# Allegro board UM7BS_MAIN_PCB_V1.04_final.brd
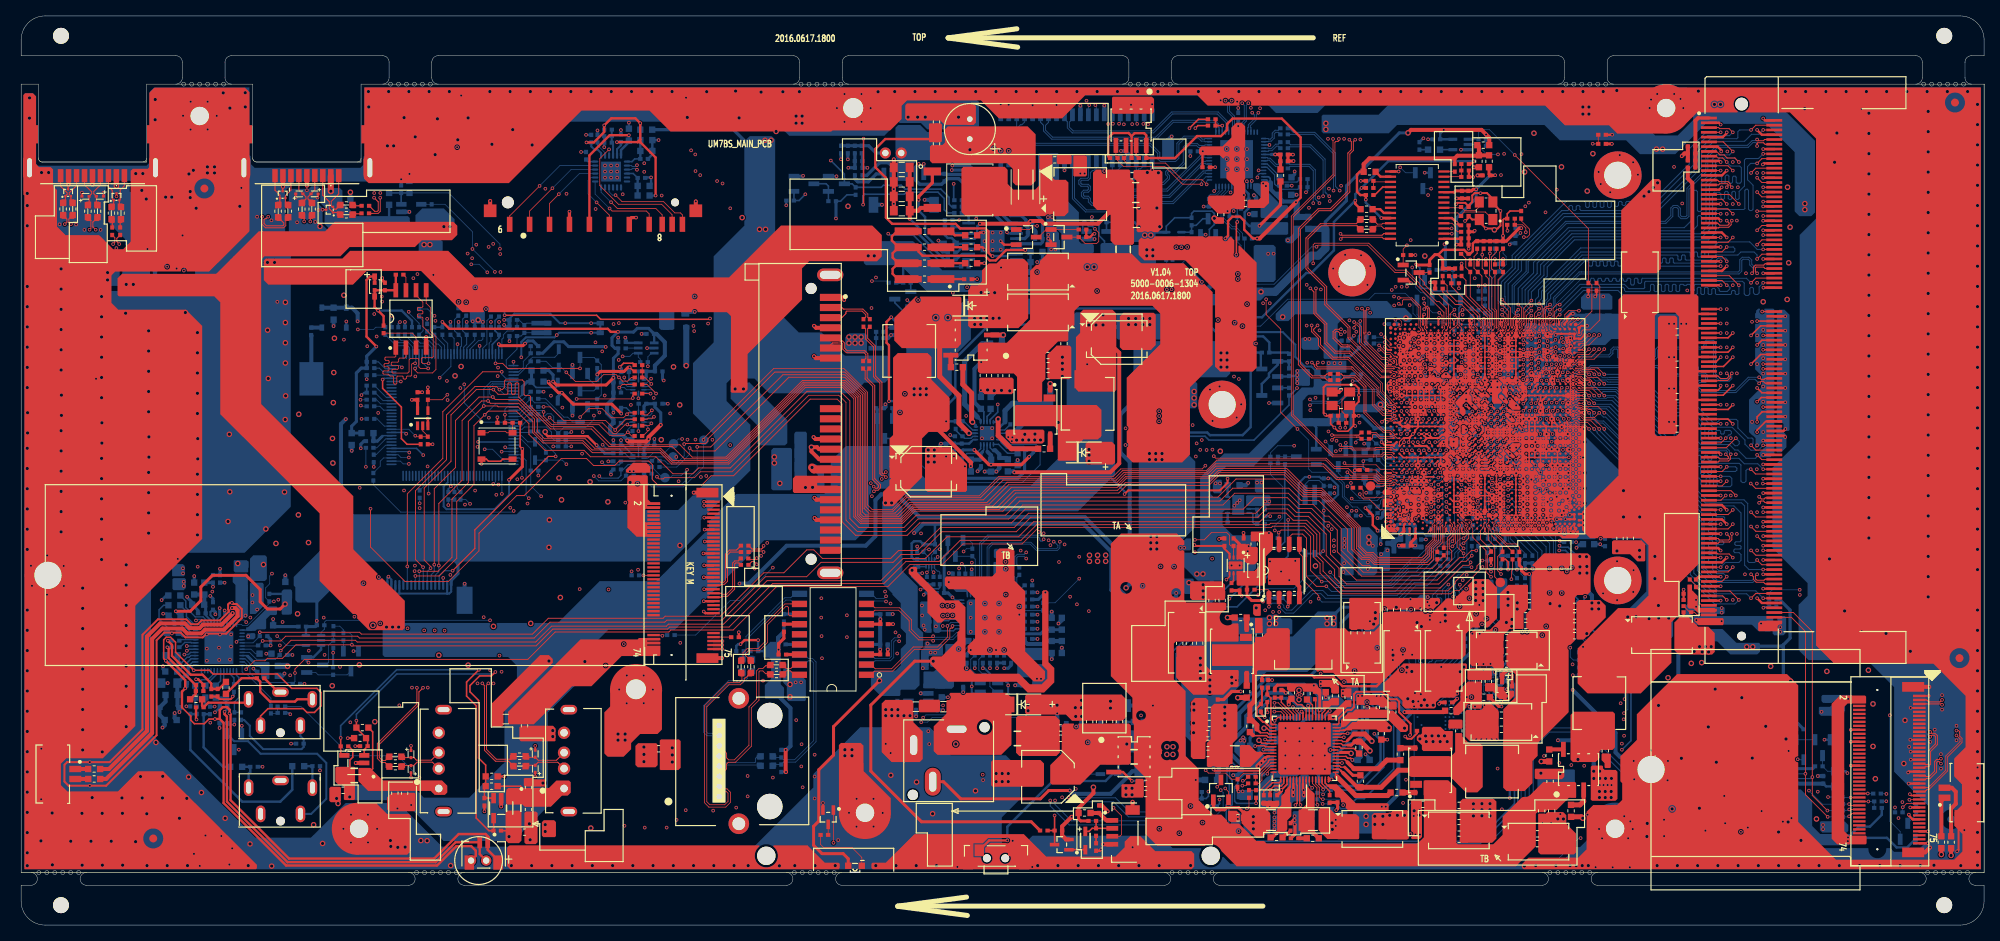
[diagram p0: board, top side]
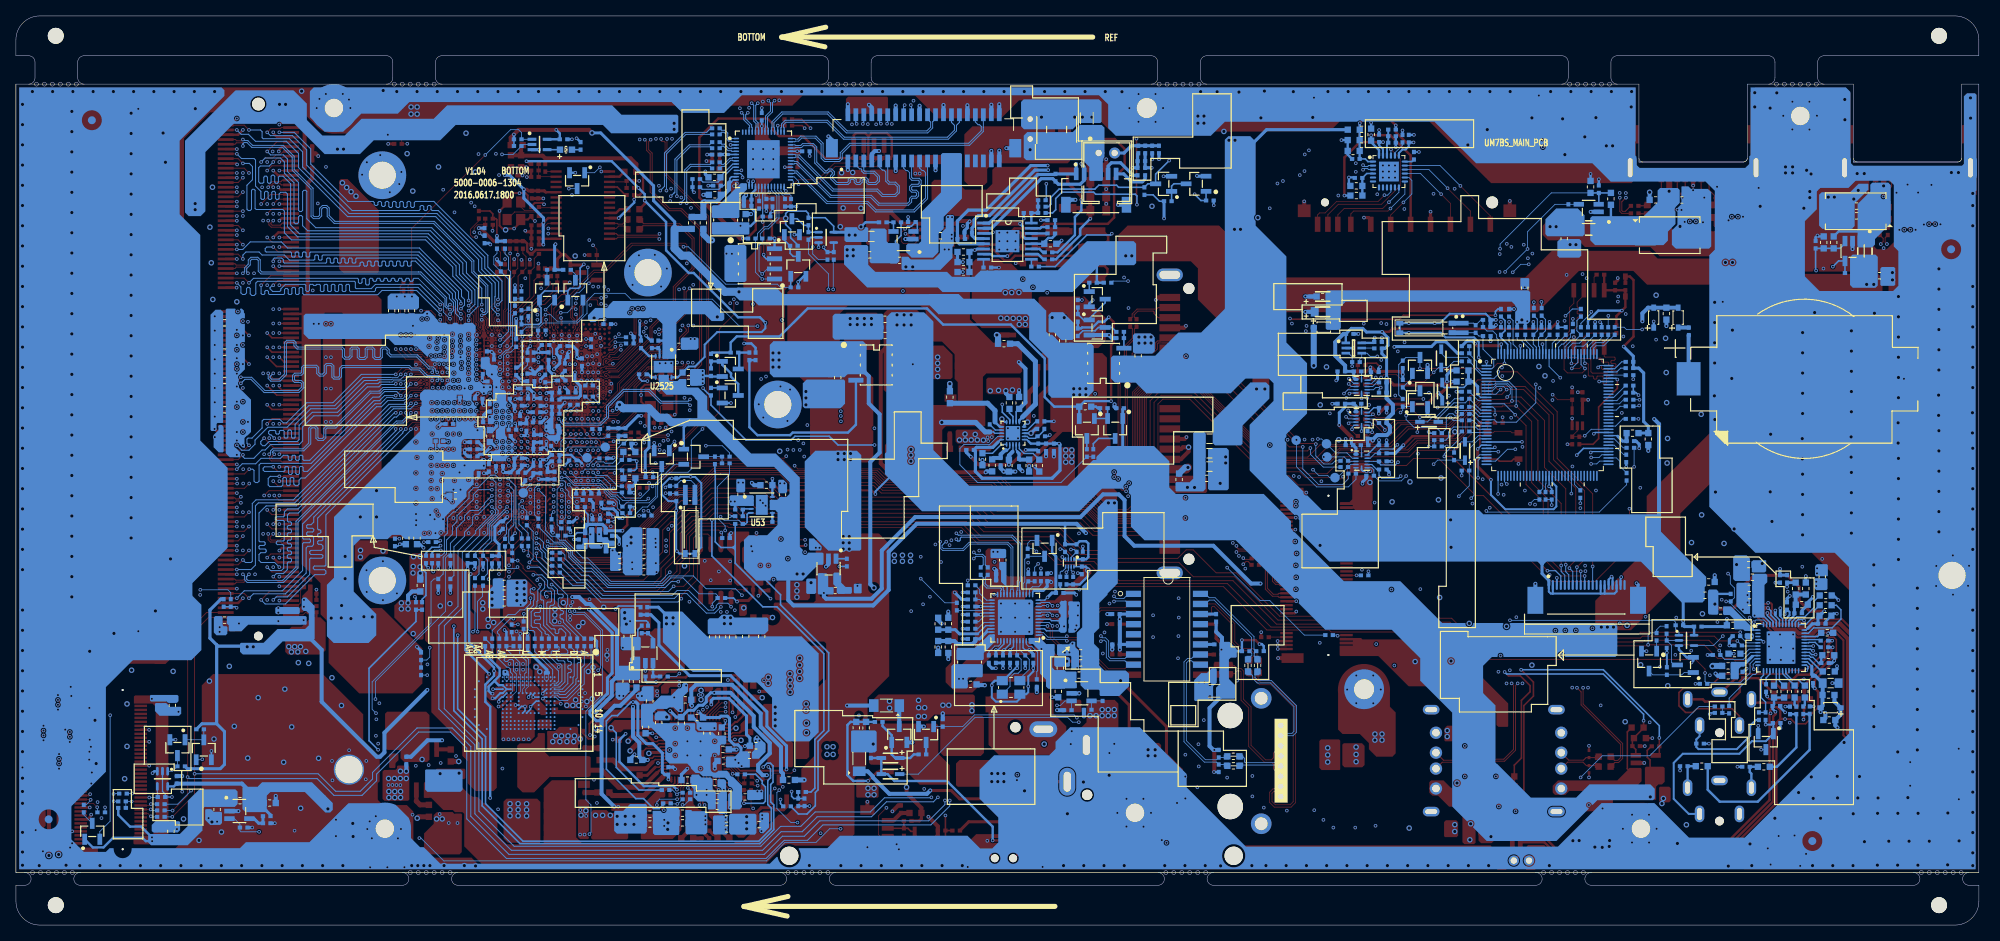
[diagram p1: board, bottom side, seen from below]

Outline 246.3 x 114.17 mm; copper layers: TOP, GND2, LAY3, LAY4, VCC5, BOTTOM. Coordinates in mm from the lower left corner of the outline.

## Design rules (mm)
net group +V3.3A_SW: nets +V3.3A_SW N5599060
net group +V5A_LDO: nets +V5A_LDO N5603445
net group AVDD33_REG: nets AVDD33_REG VDD33
net group DRVH1: nets DRVH1 DRVH1_R
net group DRVH2: nets DRVH2 DRVH2_R
net group DRVL2: nets DRVL2 DRVL2_R
net group EDP_TXN0: nets EDP_TXN0 TXN0_LVDS
net group EDP_TXN1: nets EDP_TXN1 TXN1_LVDS
net group EDP_TXP0: nets EDP_TXP0 TXP0_LVDS
net group EDP_TXP1: nets EDP_TXP1 TXP1_LVDS
net group EMMC_CLK: nets EMMC_CLK N5550076
net group EMMC_CMD: nets EMMC_CMD N5550072
net group EMMC_DATA_0: nets EMMC_DATA_0 N5550120
net group EMMC_DATA_1: nets EMMC_DATA_1 N5550080
net group EMMC_DATA_2: nets EMMC_DATA_2 N5550068
net group EMMC_DATA_3: nets EMMC_DATA_3 N5550084
net group EMMC_DATA_4: nets EMMC_DATA_4 N5550136
net group EMMC_DATA_5: nets EMMC_DATA_5 N5550132
net group EMMC_DATA_6: nets EMMC_DATA_6 N5550116
net group EMMC_DATA_7: nets EMMC_DATA_7 N5550128
net group EMMC_RESET: nets EMMC_RESET N5550124
net group HDA_BITCLK: nets HDA_BITCLK N65040
net group HDA_SDATAIN0: nets HDA_SDATAIN0 N65098
net group HDA_SYNC: nets HDA_SYNC N65002
net group HSON: nets HSON PCIE_RXN0_LAN
net group HSOP: nets HSOP PCIE_RXP0_LAN
net group LAN_TX0N: nets LAN_TX0N N1052644
net group LAN_TX0P: nets LAN_TX0P N1052618
net group LAN_TX1N: nets LAN_TX1N N1052610
net group LAN_TX1P: nets LAN_TX1P N1052708
net group LAN_TX2N: nets LAN_TX2N N1052530
net group LAN_TX2P: nets LAN_TX2P N1052848
net group LAN_TX3N: nets LAN_TX3N N1052868
net group LAN_TX3P: nets LAN_TX3P N1052520
net group LPC_CLK_EC: nets LPC_CLK_EC N83769
net group M_HUB_USB_P1: nets HUB_USB_PN1 HUB_USB_PP1
net group M_LAO1_CLK: nets LAO1_CLKN LAO1_CLKP
net group M_LAO1_DATA0: nets LAO1_DATAN0 LAO1_DATAP0
net group M_LAO1_DATA1: nets LAO1_DATAN1 LAO1_DATAP1
net group M_LAO1_DATA2: nets LAO1_DATAN2 LAO1_DATAP2
net group M_LAO1_DATA3: nets LAO1_DATAN3 LAO1_DATAP3
net group N73565: nets N73565 N73585
net group PCIE_TXN0_LAN: nets N60711 PCIE_TXN0_LAN
net group PCIE_TXN1_WLAN: nets N61460 PCIE_TXN1_WLAN
net group PCIE_TXP0_LAN: nets N60715 PCIE_TXP0_LAN
net group PCIE_TXP1_WLAN: nets N61464 PCIE_TXP1_WLAN
net group PMC_SLP_S0IX: nets N5595026 PMC_SLP_S0IX
net group RSMRST_PWRGD: nets N5599220 RSMRST_PWRGD
net group SATA_RXN0: nets N16952432 SATA_RXN0
net group SATA_RXP0: nets N16952428 SATA_RXP0
net group SPI_CLK: nets N7142816 SPI_CLK
net group SPI_CS0#: nets N7142786 SPI_CS0#
net group SPI_SI: nets N7142806 SPI_SI
net group SPI_SO: nets N7142796 SPI_SO
net group USB3_RX1_N: nets N16888468 USB3_RX1_N
net group USB3_RX1_P: nets N16888504 USB3_RX1_P
net group USB_PN2: nets N17343556 USB_PN2
net group USB_PN3: nets N6564823 USB_PN3
net group USB_PN4: nets N6565949 USB_PN4
net group USB_PP2: nets N17343558 USB_PP2
net group USB_PP3: nets N6564811 USB_PP3
net group USB_PP4: nets N6565995 USB_PP4
net group VCC0_SENSEP_R: nets VCC0_SENSEP_R VCC_SENSEP
net group AUDIO: nets HDA_SDATAOUT
net group CLK: nets CLK_LAN_OE# CLK_WLAN_OE# CLK_WLAN_OE#_MINI DMIC_CLK LPC_CLKRUN# SDMMC1_RCLK SMB_CLK_S2 SMBCLK SOC_SMB_CLK TBCLK
net group COMP&REF: nets AC_VREF MIC1L-VREFO MIC1R-VREFO MIC2-VREFO SODIMM_VREF_CA0 SODIMM_VREF_DQ0
net group DEFAULT: nets 5A_ONOFF +V1.8S A6 A_EARPHONE_SEL AC_PRESENT ADP_IN# BH53 BL_ADJ BT_ON DBG_UART1_RXD DBG_UART1_TXD DDI0_HPD DDI1_HPD DDR3L_EVENT DMIC_DATA DP_HPD EC_MUTE# EDP_BKLCTL EDP_BKLEN EDP_VDDEN EECS EEDI FLASH_TXE FMISO FMOSI FSCE# FSCK GA20_EC GPIO_SUS8 GPIO_SUS9 GPIO_SUS10 GPIO_SUS11 GPO H_PROCHOT# H_RCIN# HD HP_OUT_L HP_OUT_R IRQB ISOLATEB IT8928_VSS KBC_FAN_SPEED LAN_VDDEN_EC LANWAKEB LDO2-CAP LPC_SERIRQ_EC LPCPD# MIC_SEL_SPDIF N46460 N52618 N52622 N53865 N53869 N59327 N59478 N59568 N62557 N62561 N64250 N64254 N64950 N66939 N72611 N72676 N73559 N75766 N77258 N79829 N80354 N81322 N81326 N82446 N82527 N82633 N83371 N83609 N83745 N86700 N86712 N87028 N88403 N89704 N89904 N936455 N964422 N967359 N1003987 N1049332 N1051586 N1061129 N1061133 N1061141 N1062073 N1063057 N1063545 N1064125 N1064657 N1064691 N1064695 N1064865 N1091368 N1121703 N1122397 N1123071 N1123827 N1123831 N1124299 N1124955 N1125039 N1125207 N1125735 N1125963 N1126133 N1126239 N1126307 N1126437 N1126855 N1127021 N1127039 N1127083 N1127147 N1127169 N1127267 N1127313 N1127321 N1127467 N1127901 N1128819 N1129433 N5560544 N5591752 N5599330 N5601032 N5604033 N5614763 N5615595 N5615857 N5617013 N5627138 N5627940 N6729821 N6738242 N6738428 N6738432 N6738496 N6739070 N6739082 N6739106 N16712559 N16714785 PCIE_LAN_WAKE# PCIE_WIFI_WAKE# PD# PM_BATLOW# PM_SLP_S0IX# PM_SLP_S3# PM_SLP_S4# PMC_PLTRST PMC_PWRBTN# PMC_PWRBTN#_EC PMC_SLP_S3 PMC_SLP_S4 PMC_SUS_STAT# PMC_SUSPWRDNACK PMIC_EN POWSW# PROCHOT#_EC PS_LATCH# PWRONLATCHG RSET RUNTIME_SCI#_EC SA0_DIM0 SA1_DIM0 SATA_LED# SECURITY_FLASH SLPS3#_CONTROL SMB_DATA_S2 SMBDATA SMC_ONOFF# SMC_SHUTDOWN# SOC_EXTSMI# SOC_EXTSMI#_EC SOC_FLASHEN SOC_RUNTIME_SCI SOC_SMB_DATA SOC_WAKE_SCI SPKR TBDATA TP_FUSE_LDO TP_FUSE_PWR USB_OC0# USB_OC1# VBAT VFB1 VFB2 VGG_SENSEP VNN_SVID_SENSEP VREG5 WAKE_SCI_EC WIFI_PWRON WIRELESS_ON WP# XTAL1 XTAL2 XTAL25M_OUT
net group DIFFALL: nets L_OUT- M_A_DQS0 M_A_DQS1 M_A_DQS2 M_A_DQS3 M_A_DQS4 M_A_DQS5 M_A_DQS6 M_A_DQS7 M_A_DQS#0 M_A_DQS#1 M_A_DQS#2 M_A_DQS#3 M_A_DQS#4 M_A_DQS#5 M_A_DQS#6 M_A_DQS#7 M_CLK_DDR0 M_CLK_DDR1
net group ISETA: nets ISETA N16970389 N16970394
net group LL1: nets N5614603
net group LPC: nets LPC_SERIRQ
net group M_EDP: nets EDP_AUXN
net group POWER: nets +V1.05A +V1.5S +V1.5S_AUDIO +V1.8A +V1.8A_SPI +V1.8U +V1.15A +V1.15S +V1.24A +V1P8A_EMMC +V2P8A_EMMC +V3.3A +V3.3A_KBC +V3.3A_LDO +V3.3A_PRIME +V3.3A_RTC +V3.3A_WIFI +V3.3AVCC +V3.3S +V3.3S_AUDIO +V5_AVDD +V5_PVDD +V5A +V5S +V15A +V_ADP_IN +V_DC +VCCCFIOAZA +VCCDPYCSIAON_1P24 +VCCPADHSICAON_1P24 +VCCPADSSICAON_1P24 +VCORE +VDDI_EMMC +VEC_LDO +VGG +VNN +VSDIO +VSM +VSM_VTT AC_IN AGND AUDIO_DVDD_IO AVDD2 AXGND DRVH1_R_5614085 DRVH2_5615145 DRVH2_R_5614085 DRVL1 DRVL1_5614359 DRVL1_R DRVL1_R_5614085 DRVL2_5615173 DRVL2_R_5614085 ENSWREG EVDD10 GND GND_EARTH L_OUT+ LAN_CMT LAN_CMT1 LAN_CT LAN_CT1 LAN_N1 LCD_VCC LL1 LL2 LX3 LX4 LX5 N926610 N1061235 N1091486 N1126063 N5595322 N6774197 N6774217 N6835729 N6835771 R_OUT+ R_OUT- REGOUT SPK_L+ SPK_L- SPK_R+ SPK_R- VCC1_USB3.0 VCC_USB2 VDD10 VREG3 VSPI_KBC
net group RST&OK: nets BUF_PLT_RST# CORE_PWROK DDR3_VCCA_PWROK DDR3L_DRAMRST# HDA_RST# PERSTB PMC_RSTBTN RSMRST#_EC WIFI_3P3_RST# WIFI_PERST# WRST#
net group USB3_TX0_N: nets N6563083 N6564657 USB3_TX0_N
net group USB3_TX0_P: nets N6563079 N6564845 USB3_TX0_P
net group USB3_TX1_N: nets N16888488 N16888618 USB3_TX1_N
net group USB3_TX1_P: nets N16888506 N16888527 USB3_TX1_P
net group VCLK: nets N6729809 N6730049 VCLK

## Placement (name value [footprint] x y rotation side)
B1  MIC-2_0  [MIC_FOM6050MP3_190P]  57.4 8.1 180 top
C1  100NF  [CC0402N]  130.15 11.87 180 top
C2  1000pF  [CC0402N]  134.88 9.8 270 top
C3  100NF  [CC0402N]  168.66 61.85 180 top
C4  100NF  [CC0402N]  168.66 61.06 180 top
C5  100NF  [CC0402N]  164.75 68.44 180 top
C6  100NF  [CC0402N]  164.75 69.21 180 top
C7  0.022 nF  [CC0402N]  184.04 48.04 90 bottom
C8  100NF  [CC0402N]  152.89 42.49 90 top
C9  1uF  [CC0402N]  153.4 48.08 270 top
C10  1000pF  [CC0402N]  151.87 42.49 90 top
C11  100NF  [CC0402N]  150.99 48.08 270 top
C12  20PF  [CC0402N]  166.75 63.95 180 top
C13  20PF  [CC0402N]  164.78 63.96 0 top
C14  100NF  [CC0402N]  112.43 46.42 90 bottom
C15  100NF  [CC0402N]  112.56 44.54 270 bottom
C16  12pF  [CC0402N]  163.44 53.71 90 bottom
C17  100NF  [CC0402N]  169.79 55.11 0 bottom
C18  1uF  [CC0603N]  169.32 56.11 180 bottom
C19  1uF  [CC0603N]  169.33 59.42 180 bottom
C20  12pF  [CC0402N]  163.44 55.62 270 bottom
C21  100NF  [CC0402N]  78.98 60.26 0 bottom
C22  100NF  [CC0402N]  74.79 60.26 180 bottom
C23  100NF  [CC0402N]  74.79 58.23 0 bottom
C24  100NF  [CC0402N]  74.79 57.21 0 bottom
C25  1uF  [CC0402N]  183.28 57.72 180 bottom
C26  1uF  [CC0402N]  183.28 58.61 180 bottom
C27  1uF  [CC0402N]  182.25 62.53 270 bottom
C28  1uF  [CC0402N]  183.79 56.83 180 bottom
C29  22uF  [CC0603N]  157.64 36.2 90 bottom
C30  22uF  [CC0603N]  158.89 36.2 90 bottom
C31  22uF  [CC0603N]  156.36 36.17 90 bottom
C32  22uF  [CC0603N]  194.93 36.33 0 top
C33  4.7uF  [CC0603N]  194.93 38.81 0 top
C34  4.7uF  [CC0603N]  186.83 61.41 270 bottom
C35  4.7uF  [CC0603N]  189.25 41.3 180 top
C36  22uF  [CC0603N]  188.79 38.83 180 top
C37  22uF  [CC0603N]  189.26 40.07 180 top
C38  4.7uF  [CC0603N]  194.93 37.56 0 top
C39  4.7uF  [CC0603N]  194.93 40.03 0 top
C40  4.7uF  [CC0603N]  195.57 42.65 270 bottom
C41  22uF  [CC0603N]  188.79 37.62 180 top
C42  1uF  [CC0402N]  188.87 58.87 180 bottom
C43  1uF  [CC0402N]  188.87 59.76 180 bottom
C44  1uF  [CC0402N]  186.85 64.96 90 bottom
C45  1uF  [CC0402N]  175.53 54.17 180 bottom
C46  1uF  [CC0402N]  180.9 59.8 180 bottom
C47  1uF  [CC0402N]  183.28 65.22 180 bottom
C48  1uF  [CC0402N]  188.87 60.64 180 bottom
C49  22uF  [CC0603N]  185.04 42.9 0 bottom
C50  22uF  [CC0603N]  185.04 41.67 0 bottom
C51  22uF  [CC0603N]  185.04 40.45 0 bottom
C52  1uF  [CC0402N]  178.72 62.69 0 bottom
C53  1uF  [CC0402N]  180.48 57.22 90 bottom
C54  22uF  [CC0603N]  170.53 46.41 0 bottom
C55  22uF  [CC0603N]  167.48 49.42 180 bottom
C56  1uF  [CC0402N]  178.58 64.2 0 bottom
C57  1uF  [CC0402N]  182.52 67.38 180 bottom
C58  1uF  [CC0402N]  173.63 54.17 0 bottom
C59  1uF  [CC0402N]  186.66 68.26 180 bottom
C60  1uF  [CC0402N]  184.8 66.11 0 bottom
C61  1uF  [CC0402N]  187.72 69.66 90 bottom
C62  1uF  [CC0402N]  185.18 58.1 90 bottom
C63  1uF  [CC0402N]  187.22 71.57 270 bottom
C64  1uF  [CC0402N]  187.21 63.15 180 bottom
C65  1uF  [CC0402N]  184.69 61.41 0 bottom
C66  1uF  [CC0402N]  186.07 58.1 90 bottom
C67  1uF  [CC0402N]  186.33 70.55 270 bottom
C68  1uF  [CC0402N]  178.58 65.09 0 bottom
C69  1uF  [CC0402N]  178.58 61.91 0 bottom
C70  1uF  [CC0402N]  188.23 66.11 180 bottom
C71  1uF  [CC0402N]  178.58 59.04 0 bottom
C72  1uF  [CC0402N]  176.42 58.36 0 bottom
C73  22uF  [CC0603N]  167.51 44.36 180 bottom
C74  22uF  [CC0603N]  167.51 45.61 180 bottom
C75  22uF  [CC0603N]  170.53 45.02 0 bottom
C76  22uF  [CC0603N]  167.48 48.15 180 bottom
C77  22uF  [CC0603N]  167.48 46.87 180 bottom
C78  1uF  [CC0402N]  180.41 61.09 90 bottom
C79  1uF  [CC0402N]  181.25 68.77 270 bottom
C80  22uF  [CC0603N]  195.98 48.58 270 bottom
C81  1uF  [CC0402N]  179.92 70.03 180 bottom
C82  1uF  [CC0402N]  190.14 66.23 180 bottom
C83  1uF  [CC0402N]  183.53 69.53 270 bottom
C84  1uF  [CC0402N]  181.3 61.09 90 bottom
C85  1uF  [CC0402N]  183.04 63.47 90 bottom
C86  1uF  [CC0402N]  175.28 70.68 90 bottom
C87  22uF  [CC0603N]  196.66 77.17 90 bottom
C88  1uF  [CC0402N]  188.23 57.22 90 bottom
C89  1uF  [CC0402N]  178.58 66.87 0 bottom
C90  1uF  [CC0402N]  179.89 68.63 270 bottom
C91  22uF  [CC0603N]  197.38 48.58 270 bottom
C92  22uF  [CC0603N]  191.15 53.91 0 bottom
C93  22uF  [CC0603N]  197.9 77.15 90 bottom
C94  22uF  [CC0603N]  199.15 77.15 90 bottom
C95  1uF  [CC0402N]  182.14 68.77 270 bottom
C96  1uF  [CC0402N]  180.95 63.13 0 bottom
C97  1uF  [CC0402N]  181.37 57.22 90 bottom
C98  1uF  [CC0402N]  172.36 53.06 0 bottom
C99  1uF  [CC0402N]  173.58 49.68 180 bottom
C100  1uF  [CC0402N]  173.59 48.42 180 bottom
C101  1uF  [CC0402N]  173.48 50.93 0 bottom
C102  1uF  [CC0402N]  170.71 61.91 270 bottom
C103  1uF  [CC0402N]  179.6 56.45 90 bottom
C104  1uF  [CC0402N]  169.82 61.91 270 bottom
C105  1uF  [CC0402N]  173.91 47.66 180 top
C106  1uF  [CC0402N]  180.48 65.67 90 bottom
C107  1uF  [CC0402N]  178.71 56.45 90 bottom
C108  1uF  [CC0402N]  182.39 56.33 90 bottom
C109  1uF  [CC0402N]  178.58 58.23 0 bottom
C110  1uF  [CC0402N]  182.52 66.11 0 bottom
C111  1uF  [CC0402N]  186.96 57.42 90 bottom
C112  1uF  [CC0402N]  185.21 50.23 270 bottom
C113  100NF  [CC0402N]  177.59 98.67 180 bottom
C114  100NF  [CC0402N]  209.07 40.83 0 top
C115  100NF  [CC0402N]  209.07 41.6 0 top
C116  100NF  [CC0402N]  209.6 96.9 0 top
C117  100NF  [CC0402N]  209.6 97.79 0 top
C118  10uF  [CC0603N]  220.11 38.29 0 bottom
C119  100NF  [CC0402N]  220.11 61.41 0 bottom
C120  100NF  [CC0402N]  220.11 60.52 0 bottom
C121  10uF  [CC0603N]  220.11 75.63 0 bottom
C122  10uF  [CC0603N]  220.11 71.95 0 bottom
C123  10uF  [CC0603N]  220.11 68.39 0 bottom
C124  10uF  [CC0603N]  220.11 64.71 0 bottom
C125  10uF  [CC0603N]  207.79 74.49 0 top
C126  10uF  [CC0603N]  207.79 70.42 0 top
C127  10uF  [CC0603N]  207.79 66.36 0 top
C128  10uF  [CC0603N]  207.79 62.3 0 top
C129  1uF  [CC0402N]  219.6 37.15 180 bottom
C130  1uF  [CC0402N]  211.85 38.95 270 bottom
C131  1uF  [CC0402N]  212.74 38.95 270 bottom
C132  1uF  [CC0402N]  210.96 38.95 270 bottom
C133  100NF  [CC0402N]  220.11 76.77 0 bottom
C134  100NF  [CC0402N]  220.11 73.09 0 bottom
C135  100NF  [CC0402N]  220.11 69.53 0 bottom
C136  100NF  [CC0402N]  220.11 65.85 0 bottom
C137  100NF  [CC0402N]  207.92 76.14 0 top
C138  100NF  [CC0402N]  207.92 72.07 0 top
C139  100NF  [CC0402N]  207.92 68.01 0 top
C140  100NF  [CC0402N]  207.92 63.95 0 top
C141  100NF  [CC0402N]  181.85 30.71 90 top
C142  4.7uF  [CC0603N]  182.86 30.58 90 top
C143  100NF  [CC0402N]  182.09 35.49 90 bottom
C144  100NF  [CC0402N]  179.09 27.96 180 top
C145  4.7uF  [CC0603N]  184.09 30.59 90 top
C146  1uF  [CC0402N]  181.15 85.45 180 top
C147  100NF  [CC0402N]  181.15 86.24 180 top
C148  100NF  [CC0402N]  181.58 91.72 90 top
C149  10uF  [CC0603N]  182.92 95.91 90 top
C150  100NF  [CC0402N]  183.85 94.14 0 top
C151  1uF  [CC0402N]  181.15 87.87 180 top
C152  100NF  [CC0402N]  180.78 91.72 90 top
C153  1uF  [CC0402N]  181.19 94.76 180 top
C154  20PF  [CC0402N]  181.15 90.17 180 top
C155  20PF  [CC0402N]  181.15 89.04 180 top
C156  1uF  [CC0603N]  121.71 57.7 270 bottom
C157  10uF  [CC0603N]  128.85 70.25 0 top
C158  10uF  [CC0603N]  128.84 71.52 0 top
C159  10uF  [CC0603N]  130.86 73 270 top
C160  0.1uF  [CC0603N]  128.84 69 180 top
C161  10uF  [CC0603N]  122.17 69 270 top
C163  0.1uF  [CC0603N]  120.73 69.02 90 top
C164  10uF  [CC0603N]  123.58 68.99 270 top
C165  100NF  [CC0402N]  124.12 62.4 270 bottom
C166  100NF  [CC0402N]  118.15 62.78 90 bottom
C167  100NF  [CC0402N]  137.23 75.07 0 bottom
C168  2.2uF  [CC0603N]  137.26 76.07 0 bottom
C171  0.01uF  [CC0402N]  90.79 47.65 0 top
C173  2.2uF  [CC0603N]  114.96 73.37 90 bottom
C174  100NF  [CC0402N]  113.93 73.32 90 bottom
C175  1uF  [CC0603N]  121.64 65.57 270 bottom
C176  0.1uF  [CC0603N]  120.43 65.57 270 bottom
C177  100NF  [CC0402N]  111.12 59.28 90 bottom
C178  100NF  [CC0402N]  111.93 59.28 90 bottom
C179  1uF  [CC0603N]  112.13 65.1 180 bottom
C180  100NF  [CC0402N]  107.76 64.91 0 bottom
C181  100NF  [CC0402N]  109.8 64.92 0 bottom
C182  4.7uF  [CC0603N]  159.39 29.17 270 top
C183  1uF  [CC0603N]  162.31 28.28 180 bottom
C184  4.7uF  [CC0603N]  161.34 29.07 270 top
C185  10uF  [CC0603N]  190.25 10.23 0 top
C186  10uF  [CC0603N]  191.85 18.03 90 top
C187  100NF  [CC0402N]  162.33 28.83 90 top
C188  0.1uF  [CC0603N]  192.05 14.34 270 top
C189  10uF  [CC0603N]  190.25 11.46 0 top
C190  10uF  [CC0603N]  190.8 14.34 270 top
C193  4.7uF  [CC0603N]  163.7 28.5 270 top
C194  4.7uF  [CC0603N]  162.81 25.36 90 bottom
C195  10uF  [CC0603N]  149.43 40.79 90 top
C197  10uF  [CC0603N]  146.6 35.39 270 top
C198  10uF  [CC0603N]  150.69 40.79 90 top
C199  0.1uF  [CC0603N]  147.86 35.4 270 top
C200  10uF  [CC0603N]  145.37 35.38 270 top
C201  4.7uF  [CC0603N]  165.64 25.42 90 bottom
C202  100NF  [CC0402N]  202.94 48.38 270 top
C203  22uF  [CC0603N]  168.9 36.7 90 top
C204  22uF  [CC0603N]  201.92 48.57 270 top
C205  22uF  [CC0603N]  200.62 48.57 270 top
C206  22uF  [CC0603N]  173.48 39.6 90 top
C207  22uF  [CC0603N]  171.8 39.58 90 top
C208  22uF  [CC0603N]  175.26 39.6 90 top
C209  22uF  [CC0603N]  167.25 36.7 90 top
C210  10uF  [CC0603N]  170.67 24.04 270 top
C211  0.1u  [CC0603N]  154.18 24.98 90 top
C212  2.2uF  [CC0603N]  153.45 22.52 0 bottom
C213  0.1u  [CC0603N]  167.87 22.29 270 top
C214  10uF  [CC0603N]  157.53 20.61 0 bottom
C215  2.2uF  [CC0603N]  168.46 20.74 0 bottom
C216  10uF  [CC0603N]  180.42 15.03 0 top
C217  0.1uF  [CC0603N]  175.9 15.17 180 top
C218  2.2uF  [CC0603N]  160.83 26.06 0 bottom
C219  10uF  [CC0603N]  180.42 10.75 0 top
C220  10uF  [CC0603N]  180.42 12.22 0 top
C221  4.7uF  [CC0603N]  157.61 22.06 180 bottom
C222  10uF  [CC0603N]  180.42 13.66 0 top
C223  0.1u  [CC0603N]  168.05 18.05 90 top
C224  22uF  [CC0603N]  185.73 26.36 180 top
C225  22uF  [CC0603N]  185.73 24.58 180 top
C226  22uF  [CC0603N]  186.39 34.44 180 top
C227  22uF  [CC0603N]  186.4 32.77 180 top
C228  22uF  [CC0603N]  186.39 36.11 180 top
C229  22uF  [CC0603N]  149.08 25.32 180 top
C230  22uF  [CC0603N]  149.1 26.96 180 top
C231  22uF  [CC0603N]  152.72 36.23 90 bottom
C232  22uF  [CC0603N]  154.74 36.23 90 bottom
C233  100NF  [CC0402N]  155.92 15.83 90 top
C234  100NF  [CC0402N]  156.72 15.84 90 top
C235  100NF  [CC0402N]  157.61 15.84 90 top
C236  10uF  [CC0603N]  158.59 17.9 180 bottom
C237  10uF  [CC0603N]  162.04 18.21 0 bottom
C238  1uF  [CC0402N]  164.44 19.36 90 bottom
C239  22uF  [CC0603N]  166.76 13.93 0 bottom
C240  22uF  [CC0603N]  166.75 12.69 0 bottom
C241  22uF  [CC0603N]  162.67 14.05 180 bottom
C242  22uF  [CC0603N]  162.67 12.83 180 bottom
C243  100NF  [CC0402N]  165.19 15.88 90 top
C244  10uF  [CC0603N]  172.11 26.75 270 top
C245  10uF  [CC0603N]  169.62 27.31 270 top
C246  10uF  [CC0603N]  170.85 27.31 270 top
C247  10uF  [CC0603N]  168.1 27.37 270 top
C249  22uF  [CC0603N]  157.13 12.08 0 bottom
C250  22uF  [CC0603N]  153.06 12.62 180 bottom
C251  22uF  [CC0603N]  152.68 13.46 180 top
C252  22uF  [CC0603N]  157.13 13.33 0 bottom
C253  10uF  [CC0603N]  137.25 74.03 0 bottom
C254  0.01uF  [CC0402N]  144.2 68.6 90 bottom
C255  10uF  [CC0603N]  143.19 68.74 270 bottom
C256  0.01uF  [CC0402N]  153.49 71.42 270 bottom
C257  10uF  [CC0603N]  116.26 74.11 90 bottom
C258  0.01uF  [CC0402N]  104.43 71.62 270 bottom
C259  10uF  [CC0603N]  105.49 71.48 90 bottom
C260  0.01uF  [CC0402N]  107.75 73.71 180 bottom
C261  10uF  [CC0805N]  96.53 59.24 180 bottom
C263  0.01uF  [CC0402N]  90.81 46.85 0 top
C264  1uF  [CC0603N]  96.89 56.1 180 bottom
C265  1uF  [CC0603N]  169.61 36.27 90 bottom
C266  100NF  [CC0402N]  170.75 30.57 90 bottom
C267  1uF  [CC0603N]  169.73 30.64 270 bottom
C268  0.01uF  [CC0402N]  166.99 37.13 270 bottom
C281  100NF  [CC0402N]  158.47 97.55 180 bottom
C283  100NF  [CC0402N]  129.8 87.6 0 bottom
C284  10uF  [CC0603N]  130.29 86.56 180 bottom
C286  0.01uF  [CC0402N]  137.53 88.25 180 bottom
C287  100NF  [CC0402N]  158.47 98.32 180 bottom
C288  10uF  [CC0603N]  135.43 83.47 180 bottom
C290  100NF  [CC0402N]  158.47 95.02 180 bottom
C292  100NF  [CC0402N]  158.47 95.78 0 bottom
C295  100NF  [CC0402N]  152.72 101.52 270 bottom
C296  0.01uF  [CC0402N]  90.77 46.04 0 top
C297  4.7uF  [CC1206N]  111.94 101.31 90 bottom
C298  10uF  [CC1210N]  115.67 99.9 90 bottom
C299  100NF  [CC0402N]  158.47 100.06 0 bottom
C300  2.2uF  [CC0603N]  158.65 93.9 180 bottom
C301  1uF  [CC0402N]  158.34 92.85 180 bottom
C302  10uF  [CC1210N]  139.85 91.93 0 top
C303  100NF  [CC0402N]  158.47 99.29 0 bottom
C304  100NF  [CC0402N]  147.18 97.17 0 bottom
C305  1uF  [CC0402N]  158.48 95.94 180 top
C306  100NF  [CC0402N]  158.48 96.76 180 top
C307  0.01uF  [CC0402N]  158.47 96.75 180 bottom
C308  10uF  [CC0603N]  158.61 91.71 0 bottom
C309  10uF  [CC0603N]  154.75 88.53 90 bottom
C310  100NF  [CC0402N]  154.49 91.1 180 bottom
C311  0.01uF  [CC0402N]  154.49 90.32 180 bottom
C312  0.01uF  [CC0402N]  90.79 45.23 0 top
C313  100NF  [CC0402N]  77.36 56.65 270 top
C314  100NF  [CC0402N]  78.2 56.65 270 top
C315  10uF  [CC0603N]  63.16 25.03 90 top
C316  100NF  [CC0402N]  64.23 25.21 90 top
C319  10uF  [CC0805N]  96.53 57.57 0 bottom
C320  0.1u  [CC0402N]  96.89 55.07 0 bottom
C323  20PF  [CC0402N]  119.66 33.4 270 bottom
C324  20PF  [CC0402N]  120.68 33.4 270 bottom
C325  10uF  [CC0603N]  115.51 29.35 270 bottom
C326  100NF  [CC0402N]  115.79 34.19 180 bottom
C327  100NF  [CC0402N]  126.39 40 0 bottom
C328  100NF  [CC0402N]  115.34 41.7 180 bottom
C329  100NF  [CC0402N]  123.34 33.4 270 bottom
C330  100NF  [CC0402N]  115.79 34.98 180 bottom
C331  100NF  [CC0402N]  121.56 33.4 270 bottom
C332  10uF  [CC0603N]  112.7 34.17 0 bottom
C333  1uF  [CC0603N]  112.7 32.92 0 bottom
C334  100NF  [CC0402N]  111.82 27.03 180 bottom
C335  4.7uF  [CC0603N]  129.31 34.92 90 bottom
C336  100NF  [CC0402N]  126.39 35.94 0 bottom
C337  4.7uF  [CC0603N]  126.52 30.22 0 bottom
C338  100NF  [CC0402N]  114.45 40.38 180 bottom
C339  100NF  [CC0402N]  114.45 39.24 180 bottom
C340  100NF  [CC0402N]  114.45 36.99 180 bottom
C341  100NF  [CC0402N]  118.64 33.4 270 bottom
C342  100NF  [CC0402N]  116.9 43.65 90 bottom
C343  100NF  [CC0402N]  126.39 38.98 0 bottom
C344  100NF  [CC0402N]  114.45 38.09 180 bottom
C345  100NF  [CC0402N]  122.45 33.4 270 bottom
C346  100NF  [CC0402N]  125.25 44.44 270 bottom
C347  100NF  [CC0402N]  124.36 44.44 270 bottom
C348  1uF  [CC0402N]  122.84 44.08 180 bottom
C349  100NF  [CC0402N]  122.84 43.28 0 bottom
C350  100NF  [CC0402N]  108.26 33.98 180 top
C351  100NF  [CC0402N]  108.26 35.24 180 bottom
C352  100NF  [CC0402N]  95.49 30.89 0 bottom
C353  0.01uF  [CC0402N]  95.49 31.78 180 bottom
C354  1000pF  [CC1206N]  95.93 29.42 180 bottom
C355  1000pF  [CC0402N]  95.93 29.42 0 bottom
C356  0.01uF  [CC0402N]  80 21.13 180 top
C357  1000pF  [CC0402N]  80 20.33 180 top
C358  100NF  [CC0402N]  108.29 37.79 180 top
C359  100NF  [CC0402N]  108.28 39.05 180 bottom
C360  1uF  [CC0603N]  18.76 25.75 0 bottom
C361  1uF  [CC0603N]  28.9 45.27 180 bottom
C362  100NF  [CC0402N]  24.95 43.48 90 bottom
C363  4.7uF  [CC0603N]  18.89 33.88 180 bottom
C364  2.2uF  [CC0603N]  19.03 36.7 180 bottom
C365  100NF  [CC0402N]  19.3 32.9 0 bottom
C366  10uF  [CC0603N]  18.84 31.84 180 bottom
C367  10uF  [CC0603N]  19.25 38.85 0 bottom
C368  100NF  [CC0402N]  19.71 37.83 0 bottom
C369  100NF  [CC0402N]  20.82 30.85 90 bottom
C370  10uF  [CC0805N]  18.6 30.39 180 bottom
C371  100NF  [CC0402N]  22.68 39.16 0 bottom
C372  10uF  [CC0603N]  22.22 40.23 180 bottom
C373  2.2uF  [CC0603N]  24.43 29.32 90 bottom
C374  1uF  [CC0603N]  33.9 43.09 180 bottom
C375  2.2uF  [CC0603N]  19.23 40.16 180 bottom
C376  10uF  [CC0603N]  19.22 41.39 0 bottom
C377  2.2uF  [CC0603N]  25.7 29.32 90 bottom
C378  4.7uF  [CC0603N]  21.84 29.33 90 bottom
C379  4.7uF  [CC0603N]  23.12 29.33 90 bottom
C380  100NF  [CC0402N]  28.54 39.37 180 bottom
C381  10uF  [CC0603N]  28.8 42.28 0 bottom
C382  100NF  [CC0402N]  24.07 40.07 270 bottom
C383  10uF  [CC0603N]  28.78 40.57 0 bottom
C384  100NF  [CC0402N]  31.34 27.05 90 bottom
C385  10uF  [CC0603N]  30.67 34.08 180 bottom
C386  10uF  [CC0603N]  30.87 37.64 0 bottom
C387  100NF  [CC0402N]  29.1 36.8 90 bottom
C388  100NF  [CC0402N]  29.67 32.27 90 bottom
C389  22pF  [CC0402N]  30.21 35.11 180 bottom
C390  22pF  [CC0402N]  34.54 30.29 180 bottom
C391  22pF  [CC0402N]  32.91 33.92 180 bottom
C392  22pF  [CC0402N]  30.42 36.28 180 bottom
C393  100pF  [CC0402N]  29.23 19.88 0 bottom
C394  100pF  [CC0402N]  37.02 19.95 0 bottom
C395  100NF  [CC0402N]  35.27 37.48 0 bottom
C396  100pF  [CC0402N]  22.4 30.15 0 top
C397  100pF  [CC0402N]  24.66 29.18 270 top
C398  100pF  [CC0402N]  30.04 31 0 top
C399  100pF  [CC0402N]  22.42 27.34 180 top
C400  10uF  [CC0603N]  226.85 11.77 90 bottom
C401  100NF  [CC0402N]  228.74 11.45 270 bottom
C402  100NF  [CC0402N]  227.92 11.46 270 bottom
C405  100NF  [CC0402N]  226.13 18.24 90 bottom
C409  100NF  [CC0402N]  222.13 14.7 90 bottom
C410  1uF  [CC0603N]  221.06 14.51 270 bottom
C411  1uF  [CC0603N]  214.45 15.33 180 bottom
C412  100NF  [CC0402N]  214.83 12.79 0 bottom
C413  100NF  [CC0402N]  78.95 74.24 180 bottom
C414  100NF  [CC0402N]  75.39 73.22 180 bottom
C415  10uF  [CC0603N]  56.98 79.98 270 bottom
C416  10uF  [CC0603N]  41.48 61.03 90 bottom
C417  100NF  [CC0402N]  43.73 60.77 180 bottom
C418  100NF  [CC0402N]  80 69.53 0 bottom
C419  100NF  [CC0402N]  75.79 69.43 180 bottom
C420  100NF  [CC0402N]  80 65.47 0 bottom
C421  100NF  [CC0402N]  74.79 64.96 180 bottom
C422  1uF  [CC0402N]  60.24 63.07 0 top
C423  10pF  [CC0402N]  61.75 75.11 180 bottom
C424  100NF  [CC0402N]  64.41 66.98 0 bottom
C425  10pF  [CC0402N]  61.75 73.97 180 bottom
C426  100NF  [CC0402N]  49.73 66.43 270 top
C427  100NF  [CC0402N]  45.64 80.19 90 top
C428  47pF  [CC0402N]  51.04 66.44 90 top
C429  0.01uF  [CC0402N]  106.49 75.61 90 top
C432  0.01uF  [CC0402N]  105.69 75.61 90 top
C433  0.01uF  [CC0402N]  106.42 70.36 90 top
C434  0.01uF  [CC0402N]  105.65 70.36 90 top
C435  10uF  [CC0603N]  150.11 54.04 90 bottom
C436  1uF  [CC0603N]  152.13 55.24 0 bottom
C437  10uF  [CC0603N]  12.47 81.54 180 bottom
C438  10uF  [CC0603N]  15.34 89.06 0 bottom
C439  10uF  [CC0603N]  15.34 90.29 0 bottom
C440  1000pF  [CC0402N]  13.76 92.67 0 bottom
C441  100NF  [CC0402N]  20.49 85.45 90 bottom
C442  100NF  [CC0402N]  11.43 87.13 270 top
C443  100NF  [CC0402N]  12.43 87.13 270 top
C444  10uF  [CC0603N]  52.04 86.19 270 bottom
C445  10uF  [CC0603N]  37.27 91.05 180 bottom
C446  10uF  [CC0603N]  40.56 91.06 0 bottom
C447  1000pF  [CC0402N]  37.42 92.08 180 bottom
C448  100NF  [CC0402N]  47.69 92.41 90 bottom
C449  10uF  [CC0603N]  40.4 16.93 180 top
C450  10uF  [CC0603N]  46.9 16.57 270 top
C451  10uF  [CC0603N]  48.12 16.55 270 top
C452  1000pF  [CC0402N]  49.11 16.74 270 top
C453  100NF  [CC0402N]  43 22.47 180 top
C454  10uF  [CC0603N]  63.16 11.67 0 top
C455  10uF  [CC0603N]  63.66 17.27 90 top
C456  10uF  [CC0603N]  63.66 14.52 270 top
C457  1000pF  [CC0402N]  64.74 17.41 90 top
C458  100NF  [CC0402N]  58.13 15.47 270 top
C459  0.1uF  [CC0603N]  136.57 25.55 270 top
C460  0.1uF  [CC0603N]  137.82 25.55 270 top
C461  2.2uF  [CC0805N]  112.27 27.42 0 top
C462  10uF  [CC0603N]  134.07 25.54 90 top
C464  0.1uF  [CC0603N]  135.32 25.53 270 top
C465  0.1uF  [CC0603N]  139.63 24.77 270 bottom
C466  10uF  [CC0603N]  141.1 16.52 180 top
C468  0.1uF  [CC0603N]  141.1 17.79 0 top
C488  1uF  [CC0603N]  39.21 76.78 90 bottom
C527  1uF  [CC0402N]  146.43 46.93 90 bottom
C557  1uF  [CC0402N]  145.77 42.23 0 bottom
C560  1000pF  [CC0402N]  179.36 24.52 90 top
C561  1000pF  [CC0402N]  155.13 38.68 270 top
C562  1000pF  [CC0402N]  198.99 19.6 90 top
C565  100NF  [CC0402N]  135.25 14.55 270 top
C566  100NF  [CC0402N]  76.38 56.42 180 bottom
C603  10uF  [CC1210N]  139.93 88.8 0 top
C607  0.1uF  [CC0603N]  139.38 94.1 180 top
C691  4700pF  [CC0402N]  159.79 10.9 180 top
C700  4.7uF  [CC0603N]  78.45 98.57 0 bottom
C701  0.1u  [CC0402N]  78.18 96.21 0 bottom
C702  0.1u  [CC0402N]  77.84 93.82 180 bottom
C703  2.2uF  [CC0603N]  78.11 92.82 0 bottom
C704  4.7uF  [CC0603N]  76.26 99.26 90 bottom
C705  0.1u  [CC0402N]  71.54 98.76 90 bottom
C706  1uF  [CC0402N]  70.89 96.61 270 bottom
C707  0.1u  [CC0402N]  73.64 98.25 180 bottom
C708  4.7uF  [CC0603N]  78.45 97.21 0 bottom
C710  0.1u  [CC0402N]  75.26 98.79 270 bottom
C727  470nF  [CC0402N]  116.39 88.52 180 bottom
C799  0.01uF  [CC0402N]  228.47 28.01 90 bottom
C800  10uF  [CC0603N]  226.68 27.59 90 bottom
C801  100NF  [CC0402N]  227.69 28.01 90 bottom
C822  4700pF  [CC0402N]  159.28 12.33 90 top
C823  100NF  [CC0402N]  148.14 15.42 90 bottom
C826  22uF  [CC0603N]  148.91 21.56 180 top
C827  22uF  [CC0603N]  148.91 22.81 180 top
C828  22uF  [CC0603N]  148.91 24.04 180 top
C829  10uF  [CC0603N]  158.3 16.15 180 bottom
C830  10uF  [CC0603N]  158.32 14.92 180 bottom
C831  10uF  [CC0603N]  154.25 21.32 180 bottom
C942  0.1u  [CC0402N]  129.8 88.4 0 bottom
C992  2.2uF  [CC0603N]  116.51 85.55 180 bottom
C2762  100NF  [CC0402N]  43.19 89.37 0 top
C2763  100NF  [CC0402N]  43.19 90.32 0 top
C2833  10uF  [CC5750N]  115.71 99.91 90 bottom
C2834  10uF  [CC0603N]  155.33 54.08 90 bottom
C2835  10uF  [CC0603N]  163.11 72.67 180 bottom
C2836  1uF  [CC0603N]  161.9 69.39 180 bottom
C2837  10uF  [CC0603N]  161.91 68.15 180 bottom
C2838  1000pF  [CC0402N]  131.94 96.09 0 top
CN1  0705A1BA52E/0705A1BE52E  [SMD-DDR-60X1020P-204N-R]  215.88 69.7 90 top
CN3  SAF-0001BX-41-5N-0XX  [SMD-SATA-127P-22AN-L-KX]  100.47 62.94 270 top
CN6  RJB-2X08X-XX-XX-XXX  [TH-RJ45-127P-8N]  95.04 20.6 90 top
CN7  WB1012US-02T5  [SMD-CN-100P-2N-V-CB]  58.04 7.85 0 top
CN9  213MAAA32  [SMD-M2PCIE-50X750P-75BN]  83.11 43.92 270 top
CN10  1.25T-2-2PWB-T  [SMD-CN-125P-2WBN]  243.82 16.61 90 top
CN11  F2T20U-XXT3-E  [SMD-CN-50P-20N-H]  49.21 40.38 180 bottom
CN12  1.25T-2-2PWB-T  [SMD-CN-125P-2WBN]  4.3 18.97 270 top
CN18  CN-USB-9+4  [SMD-USB-100P-9AN]  35.85 95.1 180 top
CN19  SHNG04X-XX-XX-XXX  [TH-USB-250PX200P-4BN]  53.21 20.65 90 top
CN20  SHNG04X-XX-XX-XXX  [TH-USB-250PX200P-4BN]  68.93 20.65 90 top
CN21  CDZ-1.7-V10-2010  [TH-DCIN-540P-3N]  116.39 20.6 270 top
CN22  WB2012DR-02T2  [TH-CN-200P-2N-H]  109.44 96.95 180 bottom
CN23  MC38-1200X-XXD  [SMD-SD-250P-9N]  70.6 97.25 180 top
CN24  BS-06-A3A0J001  [SMD-BATTERY-2900P-2N]  21.92 68.6 0 bottom
CN25  WB1012US-04T5  [SMD-CN-100P-4N-V-CB]  139.46 11.65 90 top
CN26  M.2 SOCKET-1 SD/DP KEY E  [SMD-M2PCIE-50X750P-75AN]  234.41 19.52 270 top
CN35  WB1003UR-40XXB  [SMD-CN-100P-40AN-H]  132.41 98.85 180 bottom
CN40  P5C08F-401665-XX  [SMD-CN-200P-8N]  113.35 84.12 90 top
CP1  330uF  [CCP7343N]  173.3 33.16 270 top
CP3  330uF  [CCP7343N]  169.55 12.07 0 top
CP4  330uF  [CCP7343N]  203.11 80.72 90 top
CP5  150uF  [CCP7343N]  137.47 73.58 0 top
CP6  220UF  [CAE630W570HN]  137.47 73.58 0 top
CP7  220UF  [CAE630W570HN]  113.57 56.93 0 top
CP8  150uF  [CCP7343N]  113.57 56.93 0 top
CP9  330uF  [CCP7343N]  205.89 36.42 0 top
CP10  330uF  [CCP7343N]  178.48 33.17 270 top
CP11  330uF  [CCP7343N]  168.25 36.7 90 top
CP12  330uF  [CCP7343N]  186.4 34.47 180 top
CP13  330uF  [CCP7343N]  185.73 25.5 180 top
CP14  100uF  [CAE660W800HN]  128.84 18.62 180 top
CP15  330uF  [CCP7343N]  127.59 82.06 180 top
CP16  330uF  [CCP7343N]  127.59 76.94 180 top
CP17  330uF  [CCP7343N]  146.26 35.45 270 top
CP18  330uF  [CCP7343N]  190.39 10.48 0 top
CP19  330uF  [CCP7343N]  180.4 11.88 0 top
CP20  330uF  [CCP7343N]  38.79 86.64 180 bottom
CP21  330uF  [CCP7343N]  15.46 89.64 0 bottom
CP50  10UF  [THR-CPR50-630X1100N]  119.04 99.96 90 top
D1  BAT54WS-7-F  [SOD1713N]  154.54 44.53 270 top
D2  SK34L  [SOD5225N]  133.33 59.35 0 top
D3  SK34L  [SOD5225N]  119.08 77.78 0 top
D4  D_2PN  [SOT95P280-3N]  108.38 62.36 270 bottom
D5  D_2PN  [SOT95P280-3N]  111.93 62.36 270 bottom
D8  1SS355TE17  [SOD2514N]  67.33 66.98 270 bottom
D9  1SS355TE17  [SOD2514N]  68.98 63.19 0 bottom
D10  1SS355TE17  [SOD2514N]  64.49 59.53 270 bottom
D11  1SS355TE17  [SOD2514N]  67.46 71.17 270 bottom
D12  BAT54WS-7-F  [SOD1713N]  44.36 80.19 270 top
D13  AOZ8231  [SOD0806N]  9.89 91.52 0 top
D14  AOZ8231  [SOD0806N]  8.08 91.52 180 top
D17  AOZ8231  [SOD0806N]  48.92 19.58 270 top
D18  AOZ8231  [SOD0806N]  48.92 21.48 90 top
D19  AOZ8231  [SOD0806N]  64.51 19.62 270 top
D20  AOZ8231  [SOD0806N]  64.51 21.52 90 top
D21  SK34L  [SOD5225N]  125.74 27.71 0 top
D22  1SS355TE17  [SOD2514N]  136.57 20.98 180 bottom
D23  1SS355TE17  [SOD2514N]  136.57 18.96 180 bottom
D26  BAT54WS-7-F  [SOD1713N]  37.73 76.28 90 bottom
D27  BAT54WS-7-F  [SOD1713N]  40.8 76.28 90 bottom
D28  1SS355TE17  [SOD2514N]  133.53 10.62 90 top
D29  1SS355TE17  [SOD2514N]  82.34 78.94 0 bottom
D30  BAT54WS-7-F  [SOD1713N]  82.2 75.07 180 bottom
D31  1SS355TE17  [SOD2514N]  82.34 77 0 bottom
D38  B2100  [SOD5336N]  126.03 92.72 90 top
D42  DFLS1100-7  [SOD2818N]  126.06 93 90 top
D43  BAT54WS-7-F  [SOD1713N]  18.61 27.3 0 bottom
D44  BAT54WS-7-F  [SOD1713N]  185.82 30.05 270 top
D2512  AOZ8231  [SOD0806N]  34.91 91.82 180 top
D2513  AOZ8231  [SOD0806N]  36.81 91.81 0 top
F2  1206L110//NANOSMDC110F  [F1206N]  14.3 84.63 90 bottom
F3  1206L110//NANOSMDC110F  [F1206N]  48.96 87.54 180 bottom
F4  1206L110//NANOSMDC110F  [F1206N]  41.8 18.78 0 top
F5  1206L110//NANOSMDC110F  [F1206N]  61.81 14.68 90 top
F6  3216FF-5A  [F1206N]  139.65 21.12 180 top
F8  3216FF-5A  [F1206N]  125.01 23.43 180 top
F9  0.5A  [F1206N]  138.29 84.86 270 top
FB1  220  [FB0603N]  184.19 95.91 90 top
FB2  220  [FB0603N]  169.2 94.59 0 top
FB4  180  [FB0603N]  150.53 89.22 90 top
FB5  180  [FB0603N]  158.02 94.13 270 top
FB6  180  [FB0603N]  160.05 88.17 270 bottom
FB7  47  [FB0603N]  79.99 22.14 0 top
FB8  180ohm  [FB0603N]  18.87 28.9 180 bottom
FB9  180ohm  [FB0603N]  28.43 43.69 0 bottom
FB10  180ohm  [FB0603N]  21.72 42.26 90 bottom
FB11  180ohm  [FB0603N]  22.99 42.26 90 bottom
FB12  180ohm  [FB0603N]  34.36 41.42 0 bottom
FB13  180ohm  [FB0603N]  32.41 39.43 180 bottom
FB14  180ohm  [FB0603N]  19.66 43.73 270 bottom
FB15  180  [FB0603N]  43.46 61.77 0 bottom
FB16  120ohm  [FB0603N]  130.42 23.46 180 top
FB17  120ohm  [FB0603N]  130.42 24.75 180 top
FB19  220  [FB0603N]  78.44 99.88 0 bottom
FB20  220  [FB0603N]  78.11 91.61 0 bottom
FB24  180  [FB0603N]  133.43 14.08 180 top
FB25  120  [FB0805N]  60.81 25.87 180 top
FB27  120  [FB0805N]  96.53 61.08 180 bottom
FB37  180  [FB0603N]  153.64 90.62 180 top
FB38  180  [FB0603N]  161.51 88.17 90 bottom
FIL1  330mA  [FIL_175P200X120-4L]  90.94 32.44 0 top
FIL2  330mA  [FIL_175P200X120-4L]  94.79 32.07 270 top
FIL3  330mA  [FIL_175P200X120-4L]  93.53 20.6 90 bottom
FIL4  330mA  [FIL_175P200X120-4L]  91.11 32.59 180 bottom
FIL5  330mA  [FIL_175P200X120-4L]  8.98 89.63 180 top
FIL6  330mA  [FIL_175P200X120-4L]  5.87 89.91 180 top
FIL7  330mA  [FIL_175P200X120-4L]  11.93 89.4 180 top
FIL9  330mA  [FIL_175P200X120-4L]  46.96 20.52 270 top
FIL10  330mA  [FIL_175P200X120-4L]  62.54 20.57 90 top
FIL11  330mA  [FIL_175P200X120-4L]  168.82 87.99 270 top
FIL14  330mA  [FIL_175P200X120-4L]  40.81 89.82 270 top
FIL15  330mA  [FIL_175P200X120-4L]  35.86 89.9 180 top
FIL16  330mA  [FIL_175P200X120-4L]  32.87 89.64 180 top
J2  PJ-358A  [TH-EARPHONE-330X400P-5N]  32.55 15.61 0 top
J3  PJ-358A  [TH-EARPHONE-330X400P-5N]  32.54 26.7 0 top
J4  CN-USB-9+4  [SMD-USB-100P-9AN]  8.95 95.1 180 top
J5  CSI-1182-06XX-CN  [SMD-CN-100P-6N-H]  110.76 90.45 180 bottom
L1  2.2uH  [LC6666N]  133.82 65.46 270 top
L2  2.2uH  [LC6666N]  111.43 72.1 270 top
L3  0.47uH  [LC6666N]  198.03 27.86 90 top
L4  0.36uH  [LC7266N]  160.88 35.49 270 top
L5  0.47uH  [LC6666N]  184.55 19.27 0 top
L6  0.47UH  [LC3225BN]  152.29 21.21 0 top
L7  0.47UH  [LC3225BN]  162.09 13.18 180 top
L8  0.47UH  [LC3225BN]  156.83 13.18 0 top
L9  2.2uH  [LC3030DL]  157.25 88.54 90 bottom
L10  2.2uH  [LC3030DL]  126.64 33.01 270 bottom
L32  10uH  [LC6666N]  132.9 91.81 180 top
LED1  LED  [LEDC0603N]  177.28 97.37 90 bottom
LED2  27-21/BHC-AN1P2/3C  [LED1706N]  104.63 7.45 180 top
MARK1  MARK  [MARK-D100D250]  23 92.49 0 top
MARK2  MARK  [MARK-D100D250]  242.65 103.29 0 top
MARK3  MARK  [MARK-D100D250]  243.22 33.52 0 top
MARK4  MARK  [MARK-D100D250]  16.58 10.88 0 top
MARK5  MARK  [MARK-D100D250]  3.48 84.87 180 bottom
MARK6  MARK  [MARK-D100D250]  236.78 101.07 180 bottom
MARK7  MARK  [MARK-D100D250]  20.9 10.55 180 bottom
MARK8  MARK  [MARK-D100D250]  242.19 13.28 180 bottom
MH1  H  [MTG340H600]  150.7 65.37 90 top
MH2  H  [MTG340H600]  200.33 43.28 90 top
MH3  H  [MTG340H600]  167 81.94 90 top
MH4  H  [MTG340H600]  200.33 94.16 90 top
MH5  H  [MTG340H580_TOP]  3.36 43.92 0 top
MH6  H  [MTG230H600]  200.01 12.1 180 bottom
MH7  H  [MTG230H600]  22.4 101.6 180 bottom
MH8  H  [MTG250H500]  104.4 102.6 0 top
MH9  H  [MTG230H600]  206.4 102.6 180 bottom
MH10  H  [MTG230H600]  105.89 14.1 180 bottom
MH11  H  [MTG340H580_TOP]  204.52 19.53 180 top
MH12  H  [MTG250H500]  77.14 29.61 0 top
MH13  H  [MTG230H600]  42.4 12.1 180 bottom
NOREF  -  [unnamed]  241.3 111.67 0 top
NOREF#2  -  [unnamed]  5 111.67 0 top
NOREF#3  -  [unnamed]  149.27 8.7 0 top
NOREF#4  -  [unnamed]  93.5 8.7 0 top
NOREF#5  -  [unnamed]  241.3 2.5 0 top
NOREF#6  -  [unnamed]  5 2.5 0 top
Q1  DTC144EUA  [SOT65P210-3N]  130.57 10.1 180 top
Q4  2N7002LT1  [SOT95P240-3N]  174.41 81.94 0 top
Q5  2N7002LT1  [SOT95P240-3N]  175.89 93.48 270 bottom
Q6  BSS138  [SOT95P280-3N]  176.1 79.73 90 bottom
Q7  BSS138  [SOT95P280-3N]  179.66 79.73 90 bottom
Q8  2N7002LT1  [SOT95P240-3N]  165.27 58.58 270 bottom
Q9  SM7302ESKP  [KPAK127P605-9N]  127.22 64.43 270 top
Q10  APM4910K  [SOIC127P600-8N]  119.21 73.47 180 top
Q13  APM4910K  [SOIC127P600-8N]  195.42 19.52 90 top
Q14  SM7302ESKP  [KPAK127P605-9N]  151.87 34.37 270 top
Q15  SM7302ESKP  [KPAK127P605-9N]  176.84 19.43 90 top
Q16  sc-70  [SOT65P210-3N]  101.26 13.54 270 top
Q18  AO4496  [SOIC127P600-8N]  138.36 70.33 180 bottom
Q19  2N7002LT1  [SOT95P240-3N]  156.67 69.83 180 bottom
Q20  2N7002LT1  [SOT95P240-3N]  156.67 66.51 180 bottom
Q21  AO4496  [SOIC127P600-8N]  109.83 70.54 0 bottom
Q22  2N7002LT1  [SOT95P240-3N]  110.63 75.04 180 bottom
Q23  2N7002LT1  [SOT95P240-3N]  110.63 78.6 180 bottom
Q30  2N7002LT1  [SOT95P240-3N]  130.22 86.39 0 top
Q31  BSS138  [SOT95P280-3N]  126.12 86.39 0 top
Q35  2N7002LT1  [SOT95P240-3N]  117.23 47.31 270 bottom
Q36  2N7002LT1  [SOT95P240-3N]  26.74 23.03 270 bottom
Q37  2N7002LT1  [SOT95P240-3N]  36.84 32.66 0 bottom
Q38  BSS138  [SOT95P280-3N]  41.38 33.15 270 bottom
Q39  2N7002LT1  [SOT95P240-3N]  226.04 22.28 270 bottom
Q40  BSS138  [SOT95P280-3N]  222.73 22.02 90 bottom
Q41  2N7002LT1  [SOT95P240-3N]  236.73 11.78 90 bottom
Q42  2N7002LT1  [SOT95P240-3N]  70.13 70.28 90 bottom
Q43  2N7002LT1  [SOT95P240-3N]  70.13 66.09 90 bottom
Q44  AO4419  [SOIC127P600-8N]  139.65 21.12 0 top
Q45  2N7002LT1  [SOT95P240-3N]  135.47 23.94 90 bottom
Q46  2N7002LT1  [SOT95P240-3N]  132.1 23.93 270 bottom
Q48  2N7002LT1  [SOT95P240-3N]  102.3 93.08 0 bottom
Q49  BSS138  [SOT95P280-3N]  98.22 93.09 0 bottom
Q50  2N7002LT1  [SOT95P240-3N]  148.94 87.7 90 bottom
Q51  BSS138  [SOT95P280-3N]  148.13 82.72 90 bottom
Q52  BSS138  [SOT95P280-3N]  150.55 16.98 90 top
Q53  BSS138  [SOT95P280-3N]  161.26 58.81 180 bottom
Q95  APM1105NUCT-TRG  [SOT229P990-3N]  117.68 92.35 270 top
R1  182  [RC0402N]  191.91 62.93 0 bottom
R2  10k  [RC0402N]  134.41 13.08 0 top
R3  100  [RC0402N]  134.88 11.68 90 top
R9  100k  [RC0402N]  164.79 16.96 180 bottom
R14  10k  [RC0402N]  182.88 76.74 270 bottom
R15  402  [RC0402N]  174.39 67.76 0 bottom
R16  150  [RC0402N]  179.85 72.84 0 bottom
R17  402  [RC0402N]  174.13 73.09 90 bottom
R18  10k  [RC0402N]  176.73 82.41 90 top
R19  100k  [RC0402N]  173.89 84.14 180 top
R20  100  [RC0402N]  177.41 49.8 180 bottom
R21  80.6  [RC0402N]  177.4 50.61 180 bottom
R22  10k  [RC0402N]  187.99 46.39 270 top
R24  0  [RC0402N]  187.13 46.4 270 top
R25  402  [RC0402N]  176.29 65.34 180 bottom
R26  10k  [RC0402N]  193.31 42.99 270 bottom
R27  10k  [RC0402N]  191.79 45.91 270 bottom
R28  10k  [RC0402N]  189.63 45.91 270 bottom
R29  10k  [RC0402N]  193.31 45.91 270 bottom
R30  75  [RC0402N]  184.04 46.25 270 bottom
R31  75  [RC0402N]  182.02 48.06 270 bottom
R32  75  [RC0402N]  182.2 50.68 270 bottom
R33  75  [RC0402N]  184.94 48.03 270 bottom
R34  75  [RC0402N]  182.83 48.07 270 bottom
R35  402  [RC0402N]  173.5 62.3 0 bottom
R36  10  [RC0402N]  178.54 46.75 0 bottom
R37  10  [RC0402N]  178.54 45.95 0 bottom
R38  10  [RC0402N]  178.54 45.11 0 bottom
R39  10  [RC0402N]  178.54 44.26 0 bottom
R40  3.3K  [RC0402N]  157.79 41.07 180 bottom
R41  3.3K  [RC0402N]  157.2 48.6 180 bottom
R42  0  [RC0603N]  154.71 47.84 90 top
R43  1k  [RC0402N]  152.13 48.08 90 top
R44  0  [RC0402N]  182.87 79.11 90 bottom
R45  200K  [RC0402N]  165.8 63.07 0 top
R46  2.49K  [RC0402N]  179.15 60.63 270 bottom
R47  49.9  [RC0402N]  171.98 61.91 270 bottom
R48  0  [RC0402N]  183.68 77.3 270 bottom
R49  49.9K  [RC0402N]  183.68 79.11 270 bottom
R50  15  [RC0402N]  167.59 54.92 0 top
R51  4.7K  [RC0402N]  179.16 81.97 270 top
R52  0  [RC0402N]  179.93 80.6 180 top
R53  4.7K  [RC0402N]  178.37 81.98 270 top
R54  4.7K  [RC0402N]  185.95 85.41 270 bottom
R55  10k  [RC0402N]  184.93 85.41 90 bottom
R56  10k  [RC0402N]  177.9 80.71 180 top
R57  10k  [RC0402N]  185.46 82.55 90 bottom
R58  100k  [RC0402N]  185.95 85.41 270 top
R59  10k  [RC0402N]  185.95 82.49 90 top
R60  100  [RC0402N]  183.53 73.09 270 bottom
R61  100k  [RC0402N]  185.13 85.41 270 top
R62  1k  [RC0402N]  114.66 47.34 90 bottom
R63  4.7K  [RC0402N]  184.93 82.49 270 top
R64  1k  [RC0402N]  113.21 47.34 90 bottom
R65  1k  [RC0402N]  191.79 42.99 270 bottom
R66  10k  [RC0402N]  179.94 81.97 270 top
R67  1k  [RC0402N]  181.15 84.29 0 top
R68  10k  [RC0402N]  182.69 85.41 90 top
R69  10k  [RC0402N]  113.64 43.26 90 bottom
R70  10k  [RC0402N]  114.48 43.26 90 bottom
R71  4.7K  [RC0402N]  184.32 85.41 270 top
R72  10k  [RC0402N]  115.27 43.26 270 bottom
R73  10k  [RC0402N]  183.51 85.41 90 top
R74  10k  [RC0402N]  183.79 82.49 90 top
R75  10k  [RC0402N]  180.74 81.98 90 top
R76  10k  [RC0402N]  181.83 82.49 90 top
R77  4.7K  [RC0402N]  182.77 82.49 270 top
R78  100k  [RC0402N]  177.9 79.92 0 top
R79  20K  [RC0402N]  169.8 58.41 180 bottom
R80  10k  [RC0402N]  174.72 53.38 0 bottom
R81  10M  [RC0402N]  164.23 54.67 270 bottom
R82  100k  [RC0402N]  169.55 60.46 180 bottom
R83  20K  [RC0402N]  169.77 57.1 180 bottom
R84  10k  [RC0402N]  172.61 58.61 180 bottom
R85  0  [RC0402N]  177.69 46.4 90 top
R86  100k  [RC0402N]  184.44 46.42 270 top
R87  0  [RC0402N]  178.51 46.91 90 top
R88  10k  [RC0402N]  169.73 51.73 180 bottom
R89  10k  [RC0402N]  175.39 52.49 180 bottom
R90  10k  [RC0402N]  169.73 52.55 180 bottom
R91  0  [RC0402N]  169.27 73.03 180 bottom
R92  113  [RC0402N]  169.27 73.82 180 bottom
R93  100  [RC0402N]  179.09 50.48 90 bottom
R94  402  [RC0402N]  174.39 66.36 0 bottom
R95  0  [RC0402N]  157.23 57.98 180 bottom
R97  0  [RC0402N]  157.23 58.82 180 bottom
R100  45.3  [RC0402N]  176.55 66.87 0 bottom
R101  0  [RC0402N]  193.16 60.77 0 bottom
R103  0  [RC0402N]  184 62.2 0 bottom
R105  0  [RC0402N]  155.56 27.28 90 top
R108  20K  [RC0402N]  182.87 74.95 90 bottom
R109  0  [RC0402N]  167.93 39.45 270 bottom
R111  1k  [RC0402N]  182.11 71.41 90 bottom
R113  10k  [RC0402N]  177.15 82.28 0 bottom
R115  10k  [RC0402N]  177.82 48.9 180 bottom
R118  4.7K  [RC0402N]  77.46 69.54 180 top
R119  100k  [RC0402N]  185.87 46.41 270 top
R121  100k  [RC0402N]  169.79 54.32 0 bottom
R122  10k  [RC0402N]  168.43 57.15 180 top
R123  10k  [RC0402N]  179.18 82.28 180 bottom
R124  5.6K  [RC0402N]  77.46 70.32 0 top
R125  10k  [RC0402N]  77.08 60.26 0 bottom
R126  100k  [RC0402N]  74.79 59.24 180 bottom
R127  2.2K  [RC0402N]  166.82 56.26 180 bottom
R129  0  [RC0402N]  180.98 64.4 180 bottom
R130  0  [RC0402N]  179.47 71.44 270 bottom
R131  0  [RC0402N]  177.42 70.05 270 bottom
R132  0  [RC0402N]  177.59 71.33 0 bottom
R133  0  [RC0402N]  175.65 47.95 90 bottom
R134  0  [RC0402N]  174.86 48.8 90 bottom
R135  10k  [RC0402N]  172 51.19 90 bottom
R136  0  [RC0402N]  178.58 65.98 180 bottom
R137  0  [RC0402N]  185.68 45.89 90 bottom
R138  0  [RC0402N]  186.57 45.89 90 bottom
R139  0  [RC0402N]  177.83 68.38 180 bottom
R140  0  [RC0402N]  171.52 48.41 90 bottom
R141  0  [RC0402N]  172.3 48.89 90 bottom
R142  0  [RC0402N]  177.56 72.71 0 bottom
R143  1M  [RC0402N]  183.34 98.67 0 bottom
R144  1M  [RC0402N]  183.34 97.83 0 bottom
R145  200  [RC0402N]  175.45 97.84 270 bottom
R146  10k  [RC0402N]  220.24 40.45 270 bottom
R147  10k  [RC0402N]  209.37 42.92 270 top
R148  4.7K  [RC0402N]  209.6 95.12 180 top
R149  0  [RC0402N]  219.35 40.45 270 bottom
R150  10k  [RC0402N]  210.15 42.92 90 top
R151  10k  [RC0402N]  209.07 39.29 180 top
R152  4.7K  [RC0402N]  209.6 96.01 0 top
R153  4.7K  [RC0402N]  220.62 62.93 90 bottom
R154  4.7K  [RC0402N]  220.11 59.63 0 bottom
R155  0  [RC0603N]  179.42 26.93 180 top
R156  10  [RC0402N]  174.98 35.49 270 bottom
R157  10  [RC0402N]  175.87 35.49 270 bottom
R158  10  [RC0402N]  179.43 35.49 270 bottom
R159  10  [RC0402N]  176.76 35.49 270 bottom
R160  10  [RC0402N]  180.32 35.49 270 bottom
R161  10  [RC0402N]  178.54 35.49 270 bottom
R162  10  [RC0402N]  181.21 35.49 270 bottom
R163  0  [RC0402N]  187.08 29.51 270 top
R164  10  [RC0402N]  177.65 35.49 270 bottom
R165  10  [RC0402N]  186.54 35.49 270 bottom
R166  0  [RC0402N]  184.1 37.26 270 bottom
R167  10  [RC0402N]  185.65 35.49 270 bottom
R168  10  [RC0402N]  183.87 35.49 270 bottom
R169  0  [RC0402N]  184.76 35.49 270 bottom
R170  680  [RC0402N]  181.15 87.06 180 top
R171  0  [RC0603N]  168.82 89.9 180 top
R172  0  [RC0603N]  183.47 97.94 0 top
R173  100k  [RC0402N]  169.2 91.67 180 top
R174  10k  [RC0402N]  181.19 95.57 180 top
R175  10k  [RC0402N]  179.88 95.09 270 top
R176  47K  [RC0402N]  181.18 93.95 180 top
R177  499K  [RC0402N]  169.2 92.56 0 top
R178  4.7K  [RC0402N]  169.2 93.45 180 top
R179  20K  [RC0402N]  122.75 58.19 270 bottom
R180  30k  [RC0603N]  123.81 57.72 90 bottom
R181  20K  [RC0402N]  120.44 58.08 270 bottom
R182  100K  [RC0603N]  125.03 58.5 90 bottom
R183  13k  [RC0603N]  119.17 57.7 270 bottom
R184  30k  [RC0603N]  117.9 57.7 270 bottom
R185  10k  [RC0402N]  126.57 59.66 0 bottom
R186  10k  [RC0402N]  118.02 59.98 90 bottom
R187  0  [RC0402N]  117.64 61.38 180 bottom
R188  10k  [RC0402N]  117.26 62.78 270 bottom
R189  2.2  [RC0603N]  129.12 66.28 270 bottom
R190  2.2  [RC0603N]  117.41 70.06 180 top
R191  0  [RC0603N]  128.36 59.82 180 top
R192  0  [RC0603N]  122.32 73 0 bottom
R193  0  [RC0402N]  228.11 15.18 180 bottom
R194  0  [RC0603N]  149.31 18.22 0 bottom
R195  0  [RC0402N]  157.3 29.04 270 top
R196  100k  [RC0402N]  158.12 29.04 90 top
R197  0  [RC0603N]  191.74 21.29 270 top
R198  16K  [RC0603N]  157.73 24.07 90 bottom
R199  0  [RC0603N]  194.48 14.34 270 top
R200  27k  [RC0603N]  167.29 24.84 90 bottom
R201  0  [RC0603N]  153.02 38.62 180 top
R202  0  [RC0603N]  153.78 29.32 270 top
R203  0  [RC0402N]  154.43 18.62 0 top
R204  0  [RC0603N]  172.59 16.64 0 top
R205  0  [RC0603N]  173.07 21.47 90 top
R206  0  [RC0402N]  154.43 17.8 0 top
R207  10k  [RC0402N]  155.31 18.93 180 bottom
R208  0  [RC0402N]  154.06 16.47 90 top
R209  0  [RC0603N]  159.6 24.09 270 bottom
R210  0  [RC0402N]  162.17 16.62 180 bottom
R211  10k  [RC0402N]  164.18 15.84 270 top
R213  0  [RC0603N]  164.92 28.79 90 top
R214  100k  [RC0402N]  195.46 33.76 270 bottom
R215  100k  [RC0402N]  156.15 71.89 180 bottom
R216  100k  [RC0402N]  159.08 71.26 270 bottom
R217  1k  [RC0402N]  154.27 71.42 90 bottom
R218  1M  [RC0402N]  159.08 69.43 90 bottom
R219  1k  [RC0402N]  159.09 66.98 90 bottom
R220  100k  [RC0402N]  113.08 74.45 270 bottom
R221  100k  [RC0402N]  113.06 76.25 90 bottom
R222  1k  [RC0402N]  107.75 74.49 0 bottom
R223  1k  [RC0402N]  111.15 80.66 0 bottom
R224  1M  [RC0402N]  113.07 78.03 270 bottom
R225  0  [RC0402N]  109.33 80.66 180 bottom
R227  10k  [RC0402N]  187.5 87.05 90 bottom
R228  10k  [RC0402N]  188.22 89.19 90 top
R229  10k  [RC0402N]  186.94 88.7 180 top
R230  100k  [RC0402N]  187.5 86.1 90 bottom
R231  0  [RC0603N]  168.44 30.58 90 bottom
R232  100k  [RC0402N]  181.34 71.42 270 bottom
R233  100k  [RC0402N]  186.94 87.93 0 top
R234  10k  [RC0402N]  166.83 31.22 180 bottom
R246  0  [RC0603N]  139.16 84.16 180 bottom
R247  0  [RC0805N]  138.97 86.47 0 bottom
R249  0  [RC0402N]  135.72 88.25 180 bottom
R251  10K  [RC0402N]  133.18 86.39 180 top
R253  100k  [RC0402N]  133.18 87.34 180 top
R255  100k  [RC0402N]  133.88 88.29 0 bottom
R258  10k  [RC0402N]  64.42 57.08 0 bottom
R259  0  [RC0402N]  149.39 101.19 0 top
R260  0  [RC0402N]  149.39 100.39 0 top
R262  10k  [RC0402N]  160.94 93.67 0 bottom
R263  10k  [RC0402N]  160.94 92.67 0 bottom
R266  4.99k  [RC0402N]  149.04 90.7 90 bottom
R267  4.99k  [RC0402N]  149.81 90.7 90 bottom
R268  0  [RC0402N]  153.05 90.45 270 bottom
R269  4.7K  [RC0402N]  140.71 96.32 0 top
R270  2k  [RC0402N]  138.86 96.32 0 top
R271  2k  [RC0402N]  137.1 96.32 180 top
R272  4.7K  [RC0402N]  148.7 95.16 180 top
R273  4.7K  [RC0402N]  152.12 88.98 180 bottom
R274  4.7K  [RC0402N]  151.37 90.7 270 bottom
R275  4.7K  [RC0402N]  152.14 90.7 90 bottom
R276  4.7K  [RC0402N]  152.18 86.22 0 bottom
R277  4.7K  [RC0402N]  153.97 86.22 180 bottom
R291  2.2  [RC0603N]  129.69 96.09 180 top
R294  0  [RC0603N]  115.27 32.28 270 bottom
R295  0  [RC0603N]  112.92 31.39 180 bottom
R296  0  [RC0402N]  109.95 28.62 90 bottom
R297  2.49K  [RC0402N]  118.21 30.39 270 bottom
R298  10k  [RC0402N]  126.39 37.21 180 bottom
R299  0  [RC0603N]  130.58 34.92 270 bottom
R300  10k  [RC0402N]  126.39 38.09 180 bottom
R301  10k  [RC0402N]  114.32 26.99 180 bottom
R302  0  [RC0603N]  130.58 37.84 270 bottom
R303  0  [RC0603N]  129.31 37.84 90 bottom
R304  0  [RC0402N]  128.24 39.99 90 bottom
R305  1k  [RC0402N]  126.39 40.89 0 bottom
R306  0  [RC0402N]  126.39 42.67 0 bottom
R307  15K  [RC0402N]  126.39 41.78 0 bottom
R308  0  [RC0402N]  119.35 46.79 270 bottom
R309  0  [RC0603N]  122.48 45.83 90 bottom
R310  0  [RC0402N]  117.69 43.65 90 bottom
R311  0  [RC0402N]  118.48 43.64 90 bottom
R312  0  [RC0603N]  91.57 32.44 270 top
R313  10k  [RC0402N]  119.27 43.64 90 bottom
R314  0  [RC0603N]  90.35 32.44 270 top
R315  0  [RC0603N]  94.79 31.46 180 top
R316  0  [RC0603N]  94.79 32.66 180 top
R317  1K  [RC0402N]  124.23 33.4 90 bottom
R318  0  [RC0603N]  93.54 19.99 180 bottom
R319  0  [RC0603N]  93.54 21.2 180 bottom
R320  0  [RC0603N]  90.51 32.61 270 bottom
R321  75  [RC0402N]  95.52 33.97 0 top
R322  75  [RC0402N]  95.71 37.31 90 top
R323  75  [RC0402N]  95.71 38.58 90 bottom
R324  0  [RC0402N]  95.38 19.69 270 bottom
R325  75  [RC0402N]  95.45 35.24 0 bottom
R326  0  [RC0603N]  91.71 32.6 270 bottom
R327  0  [RC0402N]  95.38 21.52 90 bottom
R328  0  [RC0402N]  92 34.39 0 bottom
R329  0  [RC0402N]  90.21 34.4 180 bottom
R330  0  [RC0402N]  24.06 43.48 90 bottom
R331  75  [RC0402N]  19.38 35.71 0 bottom
R332  75  [RC0402N]  19.37 34.89 0 bottom
R333  4.7K  [RC0402N]  25.41 27.51 0 bottom
R334  1k  [RC0402N]  22.04 26.98 270 bottom
R335  4.7K  [RC0402N]  21.23 26.99 90 bottom
R336  1k  [RC0402N]  22.9 26.96 270 bottom
R337  4.7K  [RC0402N]  23.7 26.96 90 bottom
R338  20K  [RC0402N]  26.7 29.77 270 bottom
